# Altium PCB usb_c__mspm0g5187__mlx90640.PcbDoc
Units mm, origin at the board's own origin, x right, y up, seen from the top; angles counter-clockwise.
Board outline 82 x 52 mm, 2 copper layers (Top, Bottom), stack 0 mm thick; 27 components, 19 nets, 155 pads, 65 vias.
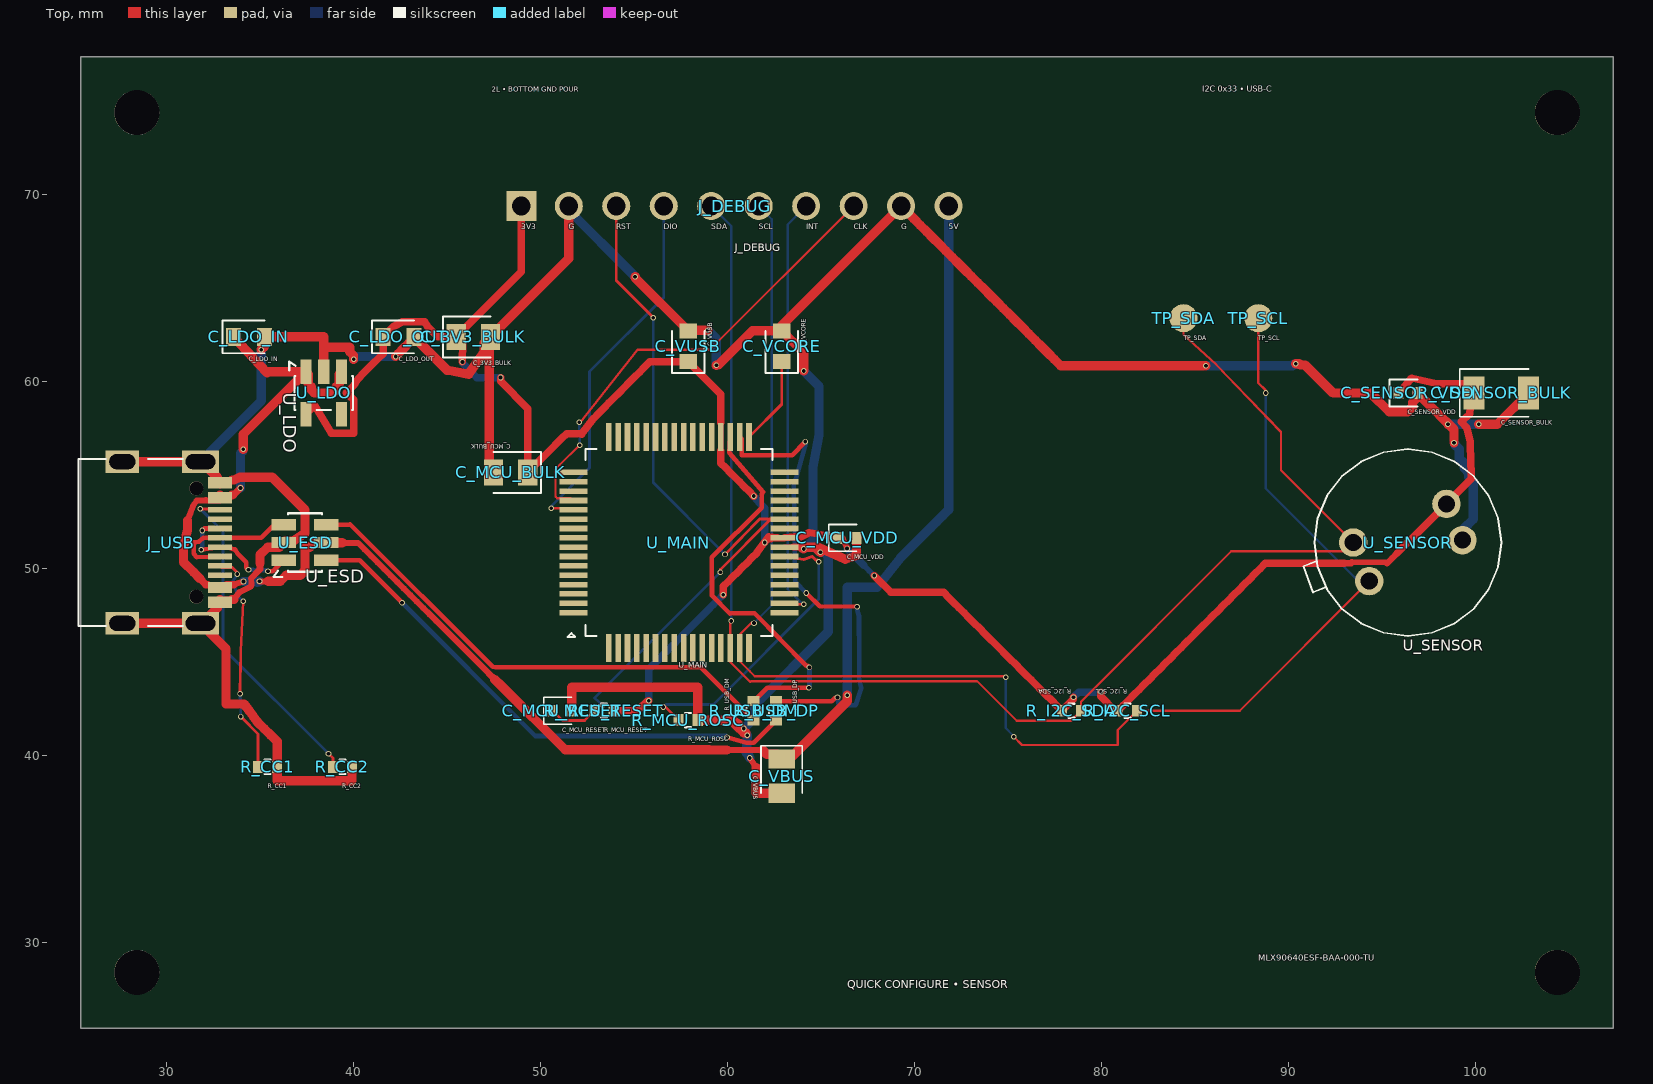
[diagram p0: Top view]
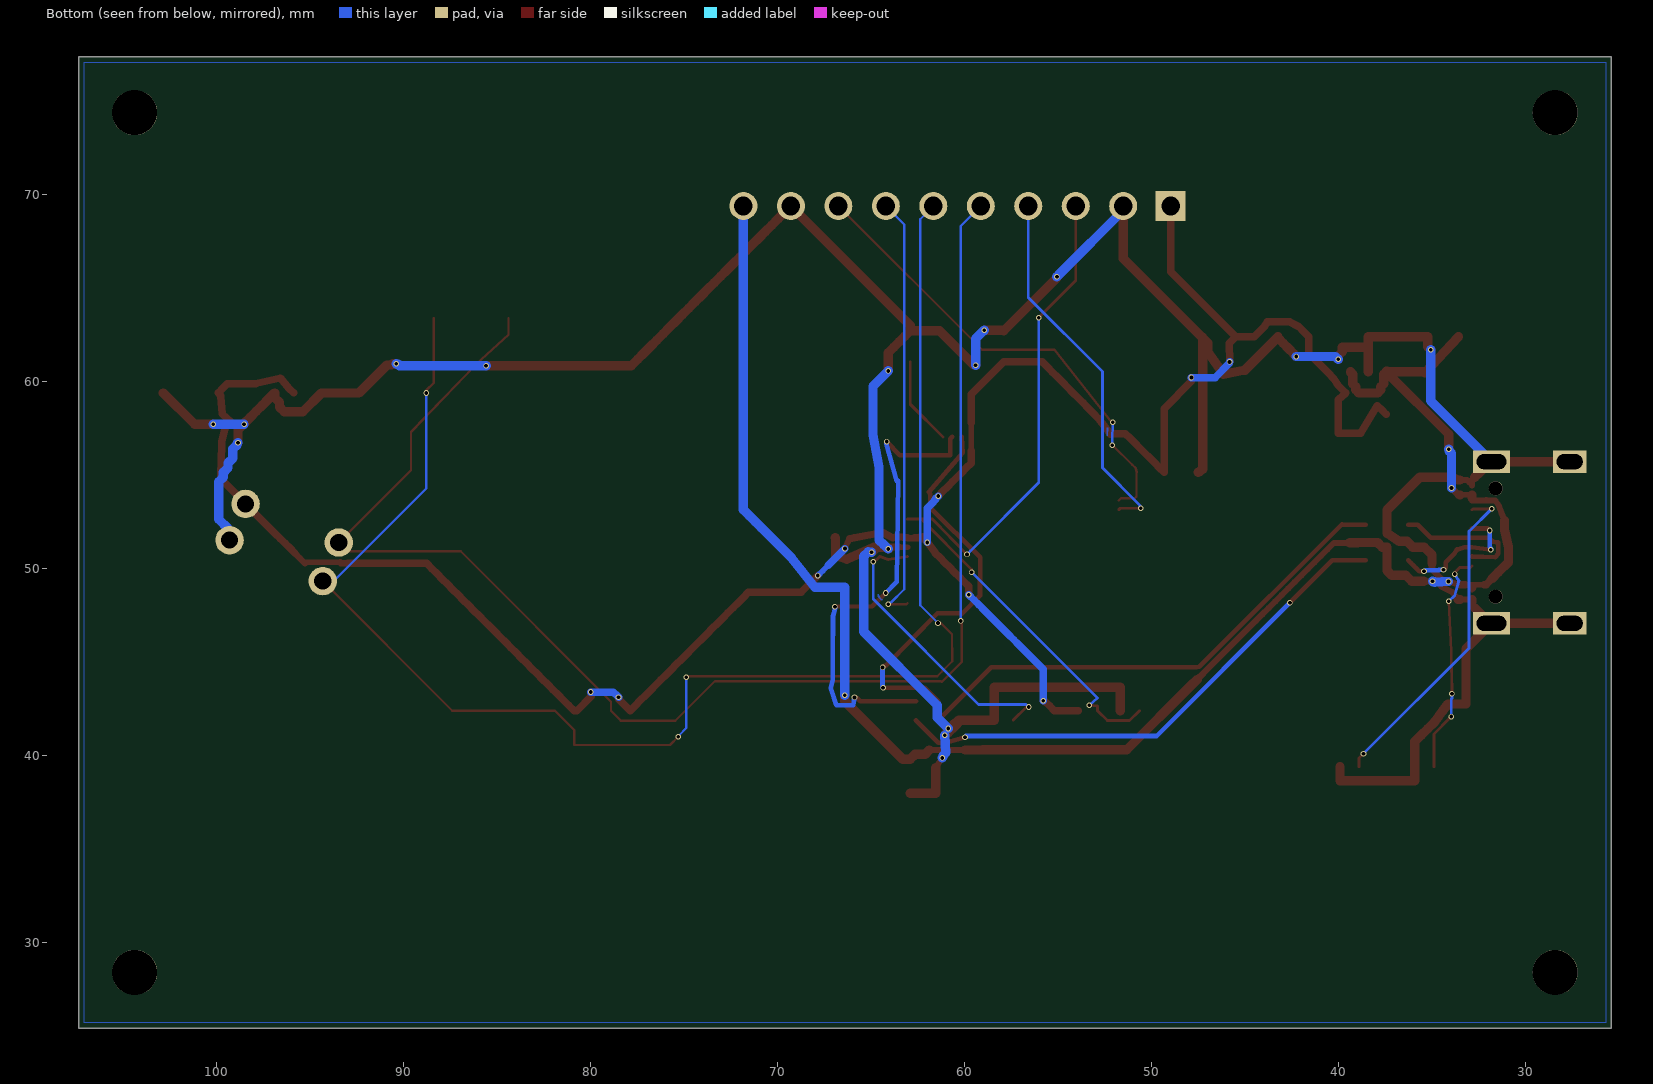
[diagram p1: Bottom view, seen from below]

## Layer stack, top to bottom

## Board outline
25.4,77.4 107.4,77.4 107.4,25.4 25.4,25.4

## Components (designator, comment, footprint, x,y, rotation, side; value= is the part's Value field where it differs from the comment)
C_3V3_BULK "" TSCIRCUIT-2.8500x1.4000mm 46.4,62.4 r0 top
C_LDO_IN "" TSCIRCUIT-2.4500x0.9500mm 34.4,62.4 r0 top
C_LDO_OUT "" TSCIRCUIT-2.4500x0.9500mm 42.4,62.4 r0 top
C_MCU_BULK "" TSCIRCUIT-2.8500x1.4000mm 48.4,55.15 r180 top
C_MCU_RESET "" TSCIRCUIT-1.5600x0.6400mm 51.15,42.4 r0 top
C_MCU_VDD "" TSCIRCUIT-1.5600x0.6400mm 66.4,51.65 r0 top
C_SENSOR_BULK "" TSCIRCUIT-4.0500x1.7500mm 101.4,59.4 r0 top
C_SENSOR_VDD "" TSCIRCUIT-1.5600x0.6400mm 96.4,59.4 r0 top
C_VBUS "" TSCIRCUIT-1.4000x2.8500mm 62.9,38.9 r270 top
C_VCORE "" TSCIRCUIT-0.9500x2.4500mm 62.9,61.9 r90 top
C_VUSB "" TSCIRCUIT-0.9500x2.4500mm 57.9,61.9 r90 top
J_DEBUG "" TSCIRCUIT-24.3600x1.5000mm 60.4,69.4 r0 top
J_USB "" TSCIRCUIT-6.7732x9.8502mm 30.113,51.4 r90 top
R_CC1 "" TSCIRCUIT-1.5600x0.6400mm 35.4,39.4 r0 top
R_CC2 "" TSCIRCUIT-1.5600x0.6400mm 39.4,39.4 r0 top
R_I2C_SCL "" TSCIRCUIT-1.5600x0.6400mm 81.4,42.4 r180 top
R_I2C_SDA "" TSCIRCUIT-1.5600x0.6400mm 78.4,42.4 r180 top
R_MCU_RESET "" TSCIRCUIT-1.5600x0.6400mm 53.4,42.4 r0 top
R_MCU_ROSC "" TSCIRCUIT-1.5600x0.6400mm 57.9,41.9 r0 top
R_USB_DM "" TSCIRCUIT-0.6400x1.5600mm 61.4,42.4 r90 top
R_USB_DP "" TSCIRCUIT-0.6400x1.5600mm 62.6,42.4 r90 top
TP_SCL "" TSCIRCUIT-1.5000x1.5000mm 88.4,63.4 r0 top
TP_SDA "" TSCIRCUIT-1.5000x1.5000mm 84.4,63.4 r0 top
U_ESD "" TSCIRCUIT-3.6000x2.5000mm 37.4,51.4 r0 top
U_LDO "" TSCIRCUIT-2.5000x3.6000mm 38.4,59.4 r270 top
U_MAIN "" TSCIRCUIT-12.8000x12.8000mm 57.4,51.4 r0 top
U_SENSOR "" TSCIRCUIT-7.3640x5.6538mm 96.4,51.4 r0 top

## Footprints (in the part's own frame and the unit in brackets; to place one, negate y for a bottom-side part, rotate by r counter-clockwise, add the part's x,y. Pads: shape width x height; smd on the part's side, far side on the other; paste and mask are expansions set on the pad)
TSCIRCUIT-0.6400x1.5600mm [mm]
  rect 0.54x0.64 smd: 1(-0.51,0) 2(0.51,0)
  silkscreen extent -0.15,-0.38 0.15,0.38
TSCIRCUIT-0.9500x2.4500mm [mm]
  rect 0.8x0.95 smd: 1(-0.825,0) 2(0.825,0)
  silkscreen extent -1.43,-0.87 0.82,0.88
TSCIRCUIT-1.4000x2.8500mm [mm]
  rect 1.025x1.4 smd: 1(-0.913,0) 2(0.913,0)
  silkscreen extent -1.62,-1.1 0.91,1.1
TSCIRCUIT-1.5000x1.5000mm [mm]
  round 1.5 smd: 1(0,0)
TSCIRCUIT-1.5600x0.6400mm [mm]
  rect 0.54x0.64 smd: 1(-0.51,0) 2(0.51,0)
  silkscreen extent -0.98,-0.72 0.51,0.72
TSCIRCUIT-2.4500x0.9500mm [mm]
  rect 0.8x0.95 smd: 1(-0.825,0) 2(0.825,0)
  silkscreen extent -1.43,-0.87 0.82,0.87
TSCIRCUIT-2.5000x3.6000mm [mm]
  rect 1.325x0.6 smd: 1(-1.137,-0.95) 2(-1.137,0) 3(-1.137,0.95) 4(1.138,0.95) 5(1.138,-0.95)
  silkscreen extent -1.69,-1.84 0.91,1.56
TSCIRCUIT-2.8500x1.4000mm [mm]
  rect 1.025x1.4 smd: 1(-0.913,0) 2(0.913,0)
  silkscreen extent -1.63,-1.1 0.91,1.1
TSCIRCUIT-3.6000x2.5000mm [mm]
  rect 1.325x0.6 smd: 1(-1.137,-0.95) 2(-1.137,0) 3(-1.137,0.95) 4(1.138,0.95) 5(1.138,0) 6(1.138,-0.95)
  silkscreen extent -1.69,-1.84 0.91,1.56
TSCIRCUIT-4.0500x1.7500mm [mm]
  rect 1.125x1.75 smd: 1(-1.463,0) 2(1.462,0)
  silkscreen extent -2.22,-1.28 1.46,1.27
TSCIRCUIT-6.7732x9.8502mm [mm]
  rect 0.3x1.3 smd: 1(-3.35,-2.737) 2(-3.05,-2.737) 3(-2.55,-2.737) 4(-2.25,-2.737) 5(-1.75,-2.737) 6(-1.25,-2.737) 7(-0.75,-2.737) 8(-0.25,-2.737) 9(0.25,-2.737) 10(0.75,-2.737) 11(1.25,-2.737) 12(1.75,-2.737) 13(2.55,-2.737) 14(2.25,-2.737) 15(3.35,-2.737) 16(3.05,-2.737)
  rect 1.2x2 hole 0.8 slot 1.6 at 90 deg: 17(-4.325,-1.693) 18(4.325,-1.693)
  rect 1.2x1.8 hole 0.8 slot 1.4 at 90 deg: 19(4.325,2.487) 20(-4.325,2.487)
  round 0.75 hole 0.75 unplated: NPTH-1(-2.9,-1.468) NPTH-2(2.9,-1.468)
  silkscreen extent -4.47,-0.75 4.47,4.83
TSCIRCUIT-7.3640x5.6538mm [mil]
  round 60 hole 36: 1(-114.96,0) 2(81.29,81.29) 3(114.96,5) 4(-81.3,-81.3)
  silkscreen extent -220,-197 197,197
TSCIRCUIT-12.8000x12.8000mm [mm]
  rect 1.5x0.3 smd: 1(-5.65,-3.75) 2(-5.65,-3.25) 3(-5.65,-2.75) 4(-5.65,-2.25) 5(-5.65,-1.75) 6(-5.65,-1.25) 7(-5.65,-0.75) 8(-5.65,-0.25) 9(-5.65,0.25) 10(-5.65,0.75) 11(-5.65,1.25) 12(-5.65,1.75) 13(-5.65,2.25) 14(-5.65,2.75) 15(-5.65,3.25) 16(-5.65,3.75) 33(5.65,3.75) 34(5.65,3.25) 35(5.65,2.75) 36(5.65,2.25) 37(5.65,1.75) 38(5.65,1.25) 39(5.65,0.75) 40(5.65,0.25) 41(5.65,-0.25) 42(5.65,-0.75) 43(5.65,-1.25) 44(5.65,-1.75) 45(5.65,-2.25) 46(5.65,-2.75) 47(5.65,-3.25) 48(5.65,-3.75)
  rect 0.3x1.5 smd: 17(-3.75,5.65) 18(-3.25,5.65) 19(-2.75,5.65) 20(-2.25,5.65) 21(-1.75,5.65) 22(-1.25,5.65) 23(-0.75,5.65) 24(-0.25,5.65) 25(0.25,5.65) 26(0.75,5.65) 27(1.25,5.65) 28(1.75,5.65) 29(2.25,5.65) 30(2.75,5.65) 31(3.25,5.65) 32(3.75,5.65) 49(3.75,-5.65) 50(3.25,-5.65) 51(2.75,-5.65) 52(2.25,-5.65) 53(1.75,-5.65) 54(1.25,-5.65) 55(0.75,-5.65) 56(0.25,-5.65) 57(-0.25,-5.65) 58(-0.75,-5.65) 59(-1.25,-5.65) 60(-1.75,-5.65) 61(-2.25,-5.65) 62(-2.75,-5.65) 63(-3.25,-5.65) 64(-3.75,-5.65)
  silkscreen extent -5.95,-5.05 5,5
TSCIRCUIT-24.3600x1.5000mm [mm]
  rect 1.6x1.6 hole 1: 1(-11.43,0)
  round 1.5 hole 1: 2(-8.89,0) 3(-6.35,0) 4(-3.81,0) 5(-1.27,0) 6(1.27,0) 7(3.81,0) 8(6.35,0) 9(8.89,0) 10(11.43,0)

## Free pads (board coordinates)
  round 2.4 hole 2.4 unplated: NPTH-3(28.4,28.4) NPTH-4(104.4,28.4) NPTH-5(28.4,74.4) NPTH-6(104.4,74.4)

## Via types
v1: diameter 0.3, hole 0.2, Top to Bottom, 65 vias

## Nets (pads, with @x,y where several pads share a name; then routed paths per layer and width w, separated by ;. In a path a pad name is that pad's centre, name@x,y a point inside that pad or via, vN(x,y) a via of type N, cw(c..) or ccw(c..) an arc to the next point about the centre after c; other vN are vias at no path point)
".J_DEBUG > .pin4 to .U_MAIN > .pin12": J_DEBUG.4 U_MAIN.12 | length 19.9
  Top w0.15: v1(50.577,53.234) 51.666,53.234 U_MAIN.12
  Bottom w0.15: v1(50.577,53.234) 50.607,53.264 50.607,53.379 52.626,55.398 52.626,60.542 56.59,64.506 J_DEBUG.4
".J_DEBUG > .pin8 to .U_MAIN > .pin13": J_DEBUG.8 U_MAIN.13 | length 25.3
  Top w0.12: U_MAIN.13 51.631,53.769 50.888,53.769 50.797,53.86 50.797,55.172 50.782,55.154 50.837,55.388 51.027,55.561 52.078,56.604 v1(52.092,56.604) ; v1(52.075,57.831) 52.104,57.817 55.187,61.707 59.057,61.707 J_DEBUG.8
  Bottom w0.12: v1(52.075,57.831) 52.097,56.816 52.094,56.813 52.094,56.606 v1(52.092,56.604)
".U_MAIN > .pin42 to .R_MCU_ROSC > .pin1": R_MCU_ROSC.1 U_MAIN.42 | length 15.8
  Top w0.15: v1(56.564,42.601) 56.689,42.601 R_MCU_ROSC.1 ; U_MAIN.42 64.078,50.491 64.533,50.65 64.722,50.461 64.804,50.461 v1(64.88,50.371)
  Bottom w0.15: v1(56.564,42.601) 56.584,42.621 56.704,42.741 59.247,42.741 64.883,48.377 v1(64.88,50.371)
GND: C_3V3_BULK.2 C_LDO_IN.2 C_LDO_OUT.2 C_MCU_BULK.2 C_MCU_RESET.2 C_MCU_VDD.2 C_SENSOR_BULK.2 C_SENSOR_VDD.2 C_VBUS.2 C_VCORE.2 C_VUSB.2 J_DEBUG.2 J_DEBUG.9 J_USB.1 J_USB.2 J_USB.15 J_USB.16 J_USB.17 J_USB.18 J_USB.19 J_USB.20 R_CC1.2 R_CC2.2 R_MCU_ROSC.2 U_ESD.2 U_LDO.2 U_MAIN.41 U_SENSOR.3 | length 211.3
  Top w0.3: J_USB.1@32.699,47.9 J_USB.1 J_USB.2@32.849,48.2 ; 32.699,54.9 J_USB.15 J_USB.16@32.849,54.6 ; J_USB.2 32.945,48.339 33.037,48.35 33.13,48.35 33.224,48.35 33.318,48.35 33.412,48.35 33.499,48.35 ; J_USB.16 J_USB.15@32.985,54.6 ; U_MAIN.41@63.501,51.15 U_MAIN.41 ; U_MAIN.41 U_MAIN.41@63.144,51.15 ; U_MAIN.41 U_MAIN.41@63.144,51.15 ; U_MAIN.41@63.144,51.15 U_MAIN.41@63.238,51.15 ; U_MAIN.41@63.144,51.15 U_MAIN.41@63.238,51.15 ; U_MAIN.41@63.238,51.15 U_MAIN.41@63.331,51.15 ; U_MAIN.41@63.238,51.15 U_MAIN.41@63.331,51.15 ; U_MAIN.41@63.331,51.15 U_MAIN.41@63.425,51.15 ; U_MAIN.41@63.331,51.15 U_MAIN.41@63.425,51.15 ; U_MAIN.41@63.425,51.15 U_MAIN.41@63.519,51.15 ; U_MAIN.41@63.425,51.15 U_MAIN.41@63.519,51.15 ; U_MAIN.41@63.519,51.15 U_MAIN.41@63.612,51.15 ; U_MAIN.41@63.519,51.15 U_MAIN.41@63.612,51.15 ; U_MAIN.41@63.612,51.15 U_MAIN.41@63.706,51.15 ; U_MAIN.41@63.612,51.15 U_MAIN.41@63.706,51.15 ; U_MAIN.41@63.706,51.15 63.8,51.15 U_MAIN.41@63.706,51.15
  Top w0.307: J_USB.16@32.985,54.6 33.114,54.743 33.499,54.741
  Top w0.31: J_USB.16 J_USB.15@32.849,54.6 ; 34.519,49.48 34.542,49.144
  Top w0.312: 33.9,48.744 34.212,48.9 34.525,49.056 34.542,49.144 ; v1(61.188,39.877) 61.359,39.617 61.53,39.357
  Top w0.325: 33.597,48.361 33.9,48.744 ; 34.519,49.48 34.758,49.727 ; 60.587,41.676 v1(60.875,41.452)
  Top w0.35: 33.597,48.361 33.599,48.35 ; 34.758,49.727 34.997,49.974 ; 60.979,41.221 v1(61.054,41.091)
  Top w0.375: 34.993,50.295 34.997,49.974 ; U_MAIN.41@63.501,51.15 63.953,51.15 ; 63.948,51.15 63.8,51.15 64.243,51.15
  Top w0.4: 63.948,51.15 v1@64.02,51.078 ; 63.953,51.15 64.404,51.15
  Top w0.475: 33.499,48.35 33.505,48.35 33.599,48.35 ; 39.8,61.6 40,61.4 v1(40,61.2) ; 66.3,50.5 66.9,50.7 C_MCU_VDD.2@66.9,51.64
  Top w0.5: J_USB.20 J_USB.17 ; J_USB.19 J_USB.18 31.874,55.725 32.474,55.125 32.699,54.9 ; J_USB.1@32.699,47.9 32.474,47.675 31.874,47.075 J_USB.17 ; J_USB.1@32.849,48.2 J_USB.2 ; 33.499,54.741 33.569,54.74 33.9,54.9 35.635,54.9 37.207,53.329 37.4,53.135 37.4,51.9 36.736,51.464 36.326,51.464 U_ESD.2 36.013,51.15 35.4,51.15 34.989,50.739 34.989,50.615 34.993,50.295 ; v1(35.058,61.713) 35.225,61.88 C_LDO_IN.2 38.4,62.4 U_LDO.2 38.4,61.85 39.8,61.85 39.8,61.6 ; R_CC2.2 39.91,38.65 35.91,38.65 R_CC1.2 35.91,39.851 35.91,40.302 35.909,40.753 35.565,41.094 35.22,41.436 34.875,41.777 34.628,42.105 34.381,42.432 34.134,42.759 33.168,42.759 33.168,45.713 J_USB.17 ; v1(42.247,61.348) 42.384,61.485 42.384,61.499 42.664,61.779 42.945,62.059 43.225,62.34 C_LDO_OUT.2 43.225,62.39 44.99,60.625 46.15,60.4 46.987,61.608 46.987,62.075 C_3V3_BULK.2 ; C_MCU_BULK.2 47.313,55.325 47.261,55.325 47.261,62.349 C_3V3_BULK.2 ; J_DEBUG.2 51.51,66.597 C_3V3_BULK.2 ; C_MCU_RESET.2 51.66,43.65 55.15,43.65 58.41,43.65 R_MCU_ROSC.2 ; v1(55.058,65.621) 55.058,65.567 C_VUSB.2 57.934,62.759 v1(58.949,62.759) ; v1(59.407,60.88) 59.424,60.897 59.512,60.897 61.339,62.725 C_VCORE.2 ; 60.587,41.676 60.3,41.9 59.828,41.9 59.355,41.9 58.883,41.9 R_MCU_ROSC.2 ; 60.979,41.221 60.878,41.221 60.539,41.56 60.199,41.9 59.752,41.9 59.304,41.9 58.857,41.9 R_MCU_ROSC.2 ; 61.53,39.357 61.53,37.988 C_VBUS.2 ; v1@64.02,51.078 64.064,51.078 v1(64.084,51.058) ; v1(64.079,60.58) 64.079,61.063 64.079,61.546 63.784,61.841 63.489,62.135 63.195,62.43 C_VCORE.2 ; 64.243,51.15 64.685,51.15 64.956,50.88 v1(64.972,50.88) ; 64.404,51.15 64.856,51.15 66.3,50.5 ; C_MCU_VDD.2@66.9,51.64 C_MCU_VDD.2 ; v1(85.595,60.859) 85.593,60.861 85.503,60.861 85.023,60.861 84.544,60.861 84.064,60.861 83.584,60.861 83.105,60.861 82.625,60.861 82.146,60.861 81.666,60.861 81.186,60.861 80.707,60.861 80.227,60.861 79.748,60.861 79.268,60.861 78.789,60.861 78.309,60.861 77.829,60.861 77.488,61.202 77.146,61.544 76.805,61.885 76.463,62.227 76.121,62.569 75.78,62.91 75.438,63.252 75.097,63.593 74.755,63.935 74.414,64.276 74.072,64.618 73.73,64.96 73.389,65.301 73.047,65.643 72.706,65.984 72.364,66.326 72.023,66.667 71.681,67.009 71.339,67.351 70.998,67.692 70.656,68.034 70.315,68.375 69.973,68.717 69.632,69.058 J_DEBUG.9 62.9,63.01 C_VCORE.2 ; v1(90.4,60.965) 90.585,60.965 90.65,60.9 90.9,60.9 92.4,59.4 94.4,59.4 95.4,58.4 96.4,58.4 96.65,58.65 96.65,58.9 96.9,59.15 96.9,59.4 C_SENSOR_VDD.2 ; v1(98.543,57.725) v1@98.543,57.767 ; v1(98.87,56.732) 98.87,57.086 98.87,57.44 v1@98.543,57.767 ; v1(100.19,57.725) 101.188,57.725 C_SENSOR_BULK.2 ; C_SENSOR_VDD.2 97.237,59.073 ; C_SENSOR_VDD.2 97.237,59.073 ; 97.237,59.073 97.563,58.747 97.89,58.42 ; 97.237,59.073 97.563,58.747 97.89,58.42 ; 97.89,58.42 98.216,58.094 ; 97.89,58.42 98.217,58.093 ; 98.216,58.094 v1@98.543,57.767 ; 98.217,58.093 v1@98.543,57.767
  Bottom w0.5: J_USB.18 35.058,58.977 v1(35.058,61.713) ; v1(40,61.2) 40.028,61.228 40.048,61.228 40.168,61.348 40.584,61.348 41,61.348 41.415,61.348 41.831,61.348 v1(42.247,61.348) ; J_DEBUG.2 51.51,69.173 54.885,65.798 54.885,65.794 v1(55.058,65.621) ; v1(58.949,62.759) 58.999,62.709 59.407,62.301 v1(59.407,60.88) ; v1(60.875,41.452) 61.457,42.035 61.457,42.694 65.4,46.637 65.4,50.65 65.15,50.9 v1(64.972,50.88) ; v1(61.054,41.091) 61.027,40.62 61,40.149 61.14,40.009 61.14,39.97 v1(61.188,39.877) ; v1(64.079,60.58) 64.9,59.759 64.9,57.15 64.578,55.446 64.578,54.955 64.577,54.464 64.576,53.973 64.575,53.482 64.575,52.991 64.574,52.5 64.573,52.009 64.572,51.518 64.328,51.288 v1(64.084,51.058) ; v1(85.595,60.859) 86.058,60.859 86.521,60.859 86.984,60.859 87.447,60.859 87.91,60.859 88.373,60.859 88.836,60.859 89.298,60.859 89.761,60.859 90.224,60.859 90.309,60.944 90.379,60.944 v1(90.4,60.965) ; v1(98.543,57.725) v1(100.19,57.725) ; v1(98.87,56.732) 98.9,56.702 98.9,56.65 99.15,56.4 99.15,55.9 99.4,55.65 99.4,55.4 99.65,55.15 99.65,54.9 99.9,54.65 99.9,52.65 99.4,52.15 99.4,51.9 99.32,51.82 U_SENSOR.3
MAIN_RESET: C_MCU_RESET.1 J_DEBUG.3 R_MCU_RESET.1 U_MAIN.38 | length 43.2
  Top w0.15: C_MCU_RESET.1 51.17,41.87 52.36,41.87 R_MCU_RESET.1 52.89,42.65 v1(53.325,42.7) ; J_DEBUG.3 54.05,65.411 56.002,63.459 v1(56.033,63.428) ; v1(59.621,49.813) 59.621,49.966 62.303,52.647 63.047,52.647 U_MAIN.38 61.727,52.65 v1(59.867,50.762)
  Bottom w0.15: v1(53.325,42.7) 52.89,43.082 59.52,49.712 v1(59.621,49.813) ; v1(56.033,63.428) 56.033,54.598 59.688,50.943 59.688,50.941 v1(59.867,50.762)
MSP_VCORE: C_VCORE.1 U_MAIN.32 | length 4.7
  Top w0.15: U_MAIN.32 62.9,58.8 C_VCORE.1
SENSOR_INT: J_DEBUG.7 U_MAIN.47 | length 23.2
  Top w0.12: U_MAIN.47 63.1,48.1 v1(64.084,48.1)
  Bottom w0.12: v1(64.084,48.1) 63.992,48.192 63.931,48.192 63.224,48.899 63.224,68.414 J_DEBUG.7
SENSOR_SCL: J_DEBUG.6 R_I2C_SCL.1 TP_SCL.1 U_MAIN.50 U_SENSOR.4 | length 83.6
  Top w0.12: v1(61.42,47.091) 61.288,47.109 60.669,46.49 60.669,45.769 U_MAIN.50 60.65,45.046 61.188,44.508 61.454,44.242 74.827,44.242 v1(74.884,44.185) ; v1(75.317,41.003) 75.752,40.568 80.884,40.568 80.884,41.374 R_I2C_SCL.1 87.4,42.4 U_SENSOR.4 ; TP_SCL.1 88.4,59.935 88.778,59.557 88.778,59.422 v1(88.8,59.4)
  Bottom w0.12: v1(61.42,47.091) 61.491,47.162 62.374,48.046 62.374,68.696 J_DEBUG.6 ; v1(74.884,44.185) 74.884,41.476 75.265,41.095 75.265,41.055 v1(75.317,41.003) ; v1(88.8,59.4) 88.8,54.287 93.635,49.452 94.218,49.452 U_SENSOR.4
SENSOR_SDA: J_DEBUG.5 R_I2C_SDA.1 TP_SDA.1 U_MAIN.51 U_SENSOR.1 | length 79.5
  Top w0.12: v1(60.203,47.205) 60.15,47.152 60.15,47 U_MAIN.51 60.15,45.003 61.212,43.94 61.252,43.98 73.355,43.98 75.472,41.863 78.4,41.863 78.4,41.89 R_I2C_SDA.1 78.91,42.883 86.955,50.928 93.008,50.928 U_SENSOR.1 89.607,55.273 89.607,57.307 86.151,60.918 84.4,62.514 TP_SDA.1
  Bottom w0.12: J_DEBUG.5 60.203,68.327 v1(60.203,47.205)
usb-dm-mcu: R_USB_DM.2 U_MAIN.30 | length 21.5
  Top w0.25: U_MAIN.30 60.1,56.2 61.9,54.1 61.839,54.002 61.833,53.264 59.163,50.613 59.175,48.553 60.126,47.602 61.446,47.618 64.22,44.814 64.288,44.813 v1(64.384,44.717) ; R_USB_DM.2 62.12,43.63 v1(64.356,43.63)
  Bottom w0.25: v1(64.356,43.63) 64.372,43.646 64.372,43.725 64.384,43.736 v1(64.384,44.717)
usb-dm-phy: R_USB_DM.1 U_ESD.4 | length 27.2
  Top w0.25: U_ESD.4 39.805,52.368 47.44,44.748 47.574,44.722 58.568,44.722 R_USB_DM.1
usb-dm-port: J_USB.7 J_USB.9 U_ESD.3 | length 7.3
  Top w0.25: J_USB.7 31.609,50.613 31.45,50.8 31.45,51.4 31.729,51.45 31.961,51.65 J_USB.9 35.065,51.65 35.764,52.349 U_ESD.3@36.262,52.349
usb-dp-mcu: R_USB_DP.2 U_MAIN.31 | length 26.3
  Top w0.25: U_MAIN.31 60.757,56.943 60.757,56.07 63.47,56.07 v1(64.161,56.8) ; R_USB_DP.2 65.582,42.91 65.771,43.099 65.874,43.099 v1(65.887,43.112) ; v1(64.214,48.7) 64.225,48.7 64.937,47.988 v1(66.935,47.956)
  Bottom w0.25: v1(64.161,56.8) 64.184,56.792 64.183,56.68 63.624,54.67 63.55,54.7 63.624,49.29 v1(64.214,48.7) ; v1(65.887,43.112) 65.95,42.7 66.85,42.7 67.15,43.6 67.046,44.064 67.047,45.333 67.035,47.45 66.928,47.873 v1(66.935,47.956)
usb-dp-phy: R_USB_DP.1 U_ESD.6 | length 28.5
  Top w0.25: U_ESD.6 40.323,50.45 42.419,48.354 42.422,48.354 v1(42.593,48.183) ; v1(59.976,40.976) 61,40.69 61.403,40.69 61.532,40.822 R_USB_DP.1
  Bottom w0.25: v1(42.593,48.183) 49.729,41.047 59.919,41.047 59.919,41.033 v1(59.976,40.976)
usb-dp-port: J_USB.8 J_USB.10 U_ESD.1 | length 7.4
  Top w0.25: v1(31.841,51.01) J_USB.8 33.05,51.15 33.25,51.15 33.65,51.025 33.774,50.827 33.936,50.665 34.098,50.504 34.259,50.342 34.259,50.197 34.259,50.053 34.371,49.941 v1(34.376,49.936) ; v1(31.898,52.041) 32.007,52.15 32.099,52.15 32.349,52.15 32.599,52.15 J_USB.10 ; v1(35.42,49.857) 35.67,49.857 35.818,50.005 35.966,50.153 36.114,50.302 U_ESD.1
  Bottom w0.25: v1(31.841,51.01) 31.828,51.029 31.828,51.071 31.898,51.14 31.898,51.366 31.898,51.591 31.898,51.816 v1(31.898,52.041) ; v1(34.376,49.936) 34.615,49.93 34.854,49.925 35.093,49.919 35.333,49.913 35.379,49.867 35.41,49.867 v1(35.42,49.857)
USB_CC1: J_USB.6 R_CC1.1 | length 12.1
  Top w0.15: J_USB.6 32.933,50.066 33.509,50.066 33.793,49.782 v1(33.776,49.71) ; v1(33.923,43.312) 33.955,45.583 v1(34.09,48.264) ; v1(33.96,42.088) 34.012,42.036 34.89,41.158 R_CC1.1
  Bottom w0.15: v1(33.776,49.71) 33.786,49.681 33.764,49.671 33.55,49.375 33.775,48.567 v1(34.09,48.264) ; v1(33.923,43.312) 33.916,43.295 33.916,43.069 33.96,43.024 v1(33.96,42.088)
USB_CC2: J_USB.12 R_CC2.1 | length 17.8
  Top w0.15: v1(31.799,53.2) 32.799,53.2 J_USB.12 ; v1(38.657,40.105) 38.688,40.074 38.688,40.066 38.89,39.864 R_CC2.1
  Bottom w0.15: v1(31.799,53.2) 31.823,53.176 32.981,52.018 33.018,52.018 33.018,45.744 v1(38.657,40.105)
VBUS5: C_LDO_IN.1 C_VBUS.1 J_DEBUG.10 J_USB.3 J_USB.4 J_USB.13 J_USB.14 U_ESD.5 U_LDO.1 U_LDO.3 | length 96
  Top w0.275: J_USB.3 J_USB.4@32.849,49
  Top w0.3: 32.086,53.65 32.467,53.65 J_USB.14 32.849,53.8 ; J_USB.4@32.199,49.15 32.474,49.15 J_USB.4 ; J_USB.3@32.849,49 J_USB.4 ; J_USB.13 32.943,53.95 33.037,53.95 33.13,53.95 33.224,53.95 33.318,53.95 33.412,53.95 33.499,53.95 ; J_USB.4@33.211,49.15 J_USB.4
  Top w0.312: 31.261,52.966 31.409,53.357 31.608,53.64
  Top w0.325: 31.113,52.575 31.261,52.966 ; 33.573,49.15 33.841,49.233 v1(34.108,49.316) ; v1(34.961,49.322) 35.426,49.322 ; 39.389,51.387 39.815,51.38 40.241,51.373 40.59,51.026 40.938,50.678 41.286,50.331 41.635,49.983 41.983,49.635 42.331,49.288 42.679,48.94 43.028,48.593 43.376,48.245 43.724,47.898 44.073,47.55 44.421,47.202 44.769,46.855 45.117,46.507 45.466,46.16 45.814,45.812 46.162,45.465 46.511,45.117 46.859,44.77 47.207,44.422 ; 59.967,40.303 60.445,40.302 60.924,40.301 61.402,40.301 61.881,40.3
  Top w0.35: 31.608,53.64 32.086,53.65 ; 47.207,44.422 47.556,44.074
  Top w0.375: 33.564,53.95 33.589,53.975 33.942,54.313 v1(33.947,54.314)
  Top w0.4: 31.77,49.477 32.099,49.15 J_USB.4@32.199,49.15 ; J_USB.4@33.211,49.15 33.573,49.15
  Top w0.45: 33.505,53.95 33.564,53.95
  Top w0.475: J_USB.13@32.849,53.8 J_USB.13 ; 33.499,53.95 33.505,53.95
  Top w0.5: 31.113,52.575 31.113,52.086 30.9,51.15 30.9,50.345 31.44,49.805 31.442,49.805 31.77,49.477 ; C_LDO_IN.1 35.373,60.475 35.436,60.537 U_LDO.1 ; v1(34.099,56.383) 34.099,57.186 U_LDO.1 ; 35.426,49.322 35.891,49.322 36.072,49.322 36.4,49.65 37.15,49.65 37.4,49.9 37.4,51.15 37.65,51.15 37.9,51.4 U_ESD.5 38.963,51.393 39.389,51.387 ; U_LDO.3 39.35,60.517 39.233,60.4 39.233,59.9 39.067,59.733 39.067,59.567 38.9,59.4 37.9,59.4 37.733,59.567 37.733,59.733 37.567,59.9 37.567,60.4 37.4,60.567 37.421,60.567 U_LDO.1 ; 47.556,44.074 47.904,43.727 51.322,40.309 56.138,40.309 56.616,40.308 57.095,40.307 57.573,40.306 58.052,40.306 58.531,40.305 59.009,40.304 59.488,40.303 59.967,40.303 ; 61.881,40.3 62.116,40.065 62.648,40.065 C_VBUS.1 63.312,39.813 66.4,42.9 v1(66.403,43.23)
  Bottom w0.5: v1(33.947,54.314) 33.947,54.779 33.947,55.244 33.947,55.709 33.947,56.174 34.058,56.286 34.058,56.342 v1(34.099,56.383) ; v1(34.108,49.316) 34.474,49.298 34.84,49.28 34.855,49.296 34.935,49.296 v1(34.961,49.322) ; v1(66.403,43.23) 66.403,49 68,49 69.258,50.58 69.579,50.903 69.901,51.225 70.222,51.548 70.544,51.87 70.865,52.192 71.187,52.515 71.508,52.837 71.83,53.159 71.83,62.51 71.83,63.002 71.83,63.495 71.83,63.987 71.83,64.479 71.83,64.971 71.83,65.463 71.83,65.955 71.83,66.447 71.83,66.939 71.83,67.432 71.83,67.924 71.83,68.416 71.83,68.908 J_DEBUG.10
VCC_3V3: C_3V3_BULK.1 C_LDO_OUT.1 C_MCU_BULK.1 C_MCU_VDD.1 C_SENSOR_BULK.1 C_SENSOR_VDD.1 C_VUSB.1 J_DEBUG.1 R_I2C_SCL.2 R_I2C_SDA.2 R_MCU_RESET.2 U_LDO.5 U_MAIN.29 U_MAIN.40 U_SENSOR.2 | length 127.1
  Top w0.3: U_MAIN.29@59.65,56.3 59.65,56.348 59.65,56.699 U_MAIN.29 59.65,57.15 59.65,57.25 59.65,57.35 59.65,57.45 59.65,57.55 59.65,57.65 59.65,57.75 59.65,57.8 ; U_MAIN.40@62.323,51.601 62.662,51.601 63.001,51.601 U_MAIN.40 U_MAIN.40@62.657,51.65 ; 66.271,51.372 66.398,51.142 v1(66.398,51.075) ; 93.4,50.35 93.76,50.35 94.12,50.35 94.48,50.35 94.84,50.35 95.2,50.35 95.29,50.29
  Top w0.312: C_MCU_VDD.1@66.144,51.603 66.271,51.372
  Top w0.325: 95.29,50.29 95.555,50.555
  Top w0.337: 95.555,50.555 95.819,50.819
  Top w0.35: 92.992,50.29 93.375,50.29 93.4,50.35
  Top w0.4: U_LDO.5 37.679,58.491 37.908,58.72 38.8,57.25 40,57.25 40,59.05 39.6,59.4 40,59.8 40.263,60.194 40.525,60.456 40.788,60.719 41.05,60.981 41.313,61.244 41.575,61.506 41.575,61.804 41.575,62.102 C_LDO_OUT.1 41.853,62.678 42.13,62.955 42.6,63.2 43.8,63.2 43.963,62.945 44.235,62.672 44.507,62.4 44.834,62.4 45.161,62.4 C_3V3_BULK.1 ; v1(45.82,61.061) 45.834,62.054 C_3V3_BULK.1 ; v1(47.862,60.226) 47.861,60.169 47.861,60.034 49.312,58.547 C_MCU_BULK.1 49.572,55.41 49.832,55.669 50.092,55.929 50.351,56.189 50.611,56.448 50.871,56.708 51.131,56.968 51.39,57.227 51.702,57.217 52.013,57.208 52.2,57.2 52.834,58.036 53.108,58.312 53.381,58.588 53.655,58.864 53.928,59.14 54.202,59.416 54.476,59.693 54.749,59.969 55.023,60.245 55.296,60.521 55.57,60.797 55.844,61.073 56.186,61.073 56.529,61.074 56.872,61.074 57.215,61.074 57.557,61.075 C_VUSB.1 59.65,59.325 59.65,57.85 59.65,57.8 ; J_DEBUG.1 48.97,65.882 C_3V3_BULK.1 ; R_MCU_RESET.2 54.23,42.4 54.55,42.4 54.871,42.4 55.191,42.4 55.445,42.654 55.699,42.909 55.722,42.909 v1(55.794,42.938) ; 59.65,56.3 59.65,55.997 59.65,55.646 59.901,55.394 60.152,55.142 60.402,54.891 60.653,54.639 60.904,54.387 61.155,54.135 v1(61.405,53.883) ; v1(59.774,48.607) 59.774,48.83 59.774,49.053 60.029,49.308 60.284,49.563 60.539,49.817 60.793,50.072 61.048,50.327 61.303,50.582 61.558,50.837 62.2,51.7 ; v1(62,51.4) 62.2,51.7 ; U_MAIN.40@62.323,51.601 62.2,51.7 ; U_MAIN.40@62.657,51.65 62.2,51.7 ; U_MAIN.40 63.6,51.7 63.85,51.65 64.386,51.933 C_MCU_VDD.1 C_MCU_VDD.1@66.144,51.603 ; v1(67.848,49.63) 67.961,49.517 68.223,49.255 68.485,48.993 68.747,48.731 69.013,48.731 69.376,48.731 69.74,48.731 70.104,48.731 70.468,48.731 70.831,48.731 71.195,48.731 71.559,48.731 71.834,48.456 72.11,48.18 72.385,47.905 72.66,47.63 72.935,47.355 73.211,47.079 73.486,46.804 73.761,46.529 74.036,46.254 74.312,45.978 74.587,45.703 74.862,45.428 75.137,45.153 75.413,44.877 75.688,44.602 75.963,44.327 76.238,44.052 76.514,43.776 76.789,43.501 77.064,43.226 77.339,42.951 77.615,42.675 R_I2C_SDA.2 78.509,43.019 v1(78.509,43.128) ; v1(80,43.4) 79.964,43.364 79.964,43.168 80.732,42.4 R_I2C_SCL.2 81.172,42.682 81.454,42.964 81.735,43.245 82.017,43.527 82.299,43.809 82.581,44.091 82.863,44.373 83.144,44.654 83.426,44.936 83.708,45.218 83.99,45.5 84.271,45.781 84.553,46.063 84.835,46.345 85.117,46.627 85.399,46.909 85.68,47.19 85.962,47.472 86.244,47.754 86.526,48.036 86.808,48.318 87.089,48.599 87.371,48.881 87.653,49.163 87.935,49.445 88.217,49.727 88.498,50.008 88.78,50.29 89.163,50.29 89.546,50.29 89.929,50.29 90.312,50.29 90.695,50.29 91.078,50.29 91.461,50.29 91.844,50.29 92.227,50.29 92.609,50.29 92.992,50.29 ; 95.819,50.819 96.084,51.084 96.348,51.348 96.613,51.613 96.877,51.878 97.142,52.142 97.407,52.407 97.671,52.671 97.936,52.936 98.2,53.2 U_SENSOR.2 98.732,53.735 98.999,54.005 99.266,54.276 99.533,54.546 99.8,54.816 99.787,55.214 99.775,55.612 99.762,56.01 99.75,56.408 99.737,56.806 99.55,57.55 99.25,57.85 99.721,58.3 99.742,58.6 99.763,58.901 99.784,59.201 99.816,59.278 C_SENSOR_BULK.1 99.686,59.652 99.434,59.904 99.054,59.904 98.674,59.904 98.295,59.904 97.915,59.904 96.6,60.2 96.142,59.652 C_SENSOR_VDD.1
  Bottom w0.3: 67.286,50.187 67.568,49.905 67.85,49.623 v1(67.848,49.63)
  Bottom w0.4: v1(45.82,61.061) 45.837,60.987 46.598,60.226 v1(47.862,60.226) ; v1(55.794,42.938) 55.794,43.276 55.794,43.614 55.794,43.951 55.794,44.289 55.794,44.627 56.058,44.891 56.322,45.155 56.586,45.419 56.85,45.683 57.114,45.947 57.378,46.211 57.642,46.475 57.906,46.739 58.171,47.004 58.435,47.268 58.699,47.532 58.963,47.796 59.227,48.06 59.491,48.324 59.755,48.588 v1(59.774,48.607) ; v1(61.405,53.883) 61.528,53.768 61.528,53.703 61.764,53.467 62,53.231 62,52.865 62,52.499 62,52.132 62,51.766 v1(62,51.4) ; v1(66.398,51.075) 66.441,51.032 66.722,50.751 67.004,50.469 67.286,50.187 ; v1(78.509,43.128) 78.573,43.192 78.587,43.192 78.795,43.4 v1(80,43.4)
pads on no net: J_USB.5 J_USB.11 J_USB.NPTH-1 J_USB.NPTH-2 U_LDO.4 U_MAIN.1 U_MAIN.2 U_MAIN.3 U_MAIN.4 U_MAIN.5 U_MAIN.6 U_MAIN.7 U_MAIN.8 U_MAIN.9 U_MAIN.10 U_MAIN.11 U_MAIN.14 U_MAIN.15 U_MAIN.16 U_MAIN.17 U_MAIN.18 U_MAIN.19 U_MAIN.20 U_MAIN.21 U_MAIN.22 U_MAIN.23 U_MAIN.24 U_MAIN.25 U_MAIN.26 U_MAIN.27 U_MAIN.28 U_MAIN.33 U_MAIN.34 U_MAIN.35 U_MAIN.36 U_MAIN.37 U_MAIN.39 U_MAIN.43 U_MAIN.44 U_MAIN.45 U_MAIN.46 U_MAIN.48 U_MAIN.49 U_MAIN.52 U_MAIN.53 U_MAIN.54 U_MAIN.55 U_MAIN.56 U_MAIN.57 U_MAIN.58 U_MAIN.59 U_MAIN.60 U_MAIN.61 U_MAIN.62 U_MAIN.63 U_MAIN.64

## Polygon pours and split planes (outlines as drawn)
GND on Bottom (solid): 107.1,77.1 25.7,77.1 25.7,25.7 107.1,25.7
GND on Bottom (solid): 52.351,57.542 52.342,57.535 52.351,57.114
GND on Bottom (solid): 64.608,48.635 64.606,48.622 64.584,48.547 64.547,48.478 64.497,48.417 64.436,48.367 64.397,48.346 64.417,48.322 64.425,48.307 64.608,48.49

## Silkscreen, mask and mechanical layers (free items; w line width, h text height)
Top Overlay:
  text "2L • BOTTOM GND POUR" at 47.4,75.4 h0.48
  text "I2C 0x33 • USB-C" at 85.4,75.4 h0.55
  text "MLX90640ESF-BAA-000-TU" at 88.4,28.9 h0.58
  text "QUICK CONFIGURE • SENSOR" at 66.4,27.4 h0.72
